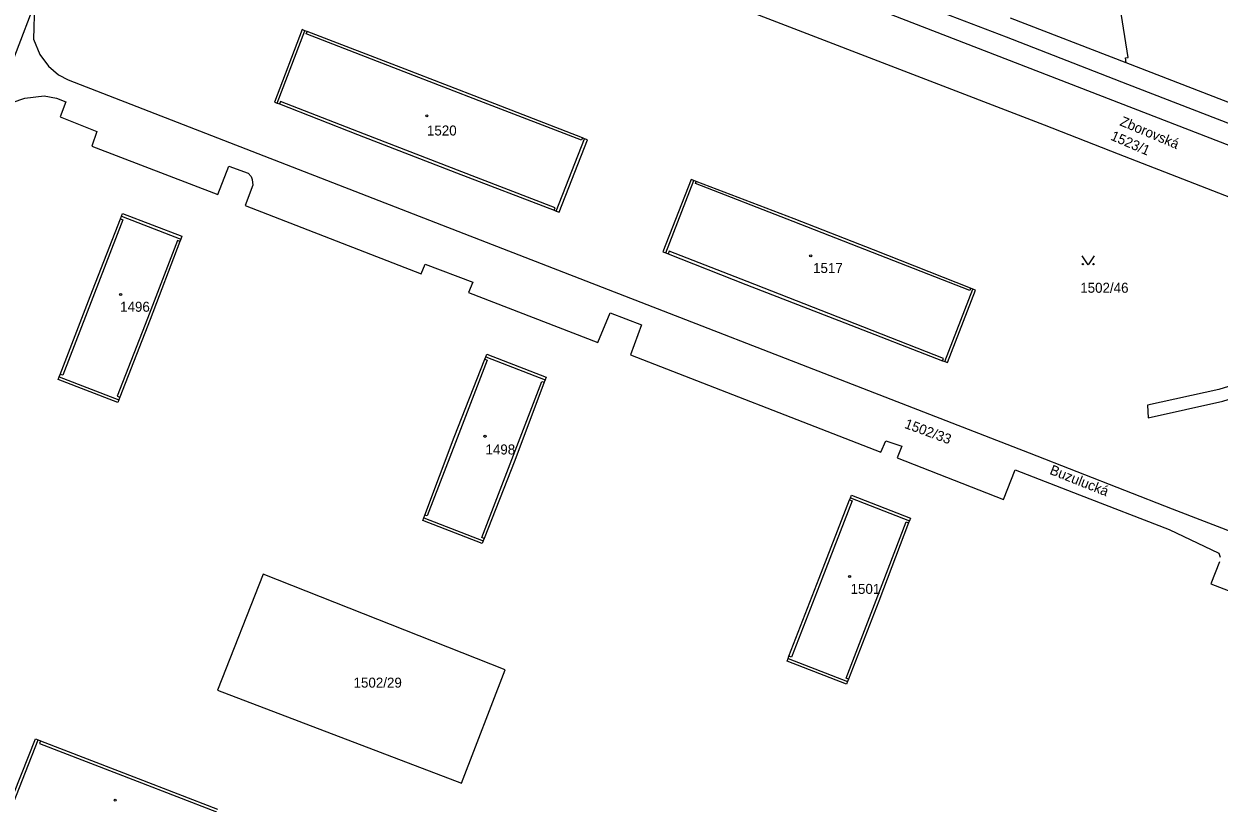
# Model space of a CAD drawing. Extents: x -737240 to -735272, y -1119606 to -1117878.
# Drawn here: x -736749.6 to -736546.3, y -1118575.4 to -1118442.9 of the extents above; entities that cross this region are included whole.
import ezdxf

# ---------------------------------------------------------------- set-up
doc = ezdxf.new("R2010")
doc.units = 0
for name, color, linetype in [('Level 1', 7, 'Continuous'), ('Level 15', 7, 'Continuous'), ('Level 18', 7, 'Continuous'), ('Level 19', 7, 'Continuous'), ('Level 25', 7, 'Continuous'), ('Level 4', 7, 'Continuous')]:
    doc.layers.add(name, color=color, linetype=linetype)

msp = doc.modelspace()

# ---------------------------------------------------------------- linework, layer by layer
at = {"layer": 'Level 1'}
for p, q in [((-736747.83, -1118439.49), (-736756.5, -1118461.9)), ((-736562.09, -1118449.5), (-736581.74, -1118441.93)), ((-736701.44, -1118444.19), (-736701.8, -1118444.05)), ((-736706.51, -1118456.37), (-736706.14, -1118456.51)), ((-736654.21, -1118462.42), (-736654.56, -1118462.28)), ((-736635.22, -1118469.69), (-736635.62, -1118469.53)), ((-736733.2, -1118476.05), (-736733.03, -1118475.61)), ((-736659.38, -1118474.6), (-736659.03, -1118474.74)), ((-736722.91, -1118479.5), (-736723.07, -1118479.91)), ((-736640.41, -1118481.84), (-736640.01, -1118482)), ((-736588.16, -1118487.99), (-736588.54, -1118487.84)), ((-736671.21, -1118499.94), (-736671.05, -1118499.54)), ((-736593.33, -1118500.18), (-736592.94, -1118500.33)), ((-736743.6, -1118502.94), (-736743.44, -1118502.51)), ((-736660.94, -1118503.44), (-736661.1, -1118503.86)), ((-736733.3, -1118506.4), (-736733.46, -1118506.82)), ((-736609.12, -1118523.87), (-736608.98, -1118523.5)), ((-736681.57, -1118526.89), (-736681.4, -1118526.44)), ((-736598.94, -1118527.4), (-736599.09, -1118527.78)), ((-736671.31, -1118530.41), (-736671.47, -1118530.81)), ((-736619.59, -1118550.84), (-736619.45, -1118550.46)), ((-736609.31, -1118554.34), (-736609.46, -1118554.73)), ((-736747.19, -1118564.68), (-736746.78, -1118564.84))]:
    msp.add_line(p, q, dxfattribs=at)
for points in [[(-736738.29, -1118405.68), (-736735.87, -1118406.26), (-736735.1, -1118404.8), (-736733.22, -1118403), (-736731.82, -1118402.29), (-736730.44, -1118401.87), (-736728.42, -1118401.73), (-736726.37, -1118402.09), (-736697.48, -1118413.17), (-736643.97, -1118433.86), (-736576.05, -1118460.06), (-736563.41, -1118465.01), (-736498.48, -1118490.24)], [(-736562.09, -1118449.5), (-736562.21, -1118448.68), (-736561.72, -1118448.62), (-736566.43, -1118418.97), (-736566.87, -1118418.7)], [(-736619.24, -1118430.87), (-736611.06, -1118434.15), (-736582.47, -1118445.12), (-736561.82, -1118453.17), (-736494.82, -1118479.04), (-736481.98, -1118484.08), (-736468.17, -1118487.49), (-736434.16, -1118500.61), (-736418.43, -1118506.54), (-736407.15, -1118511.19), (-736401.23, -1118513.16)], [(-736616.1, -1118435.8), (-736505.66, -1118478.59), (-736444.34, -1118502.39), (-736415.66, -1118513.25), (-736415.08, -1118513.68), (-736401.23, -1118513.16)], [(-736747.83, -1118439.49), (-736747.99, -1118445.49), (-736746.92, -1118448.11), (-736745.44, -1118450.08), (-736743.76, -1118451.55), (-736742.12, -1118452.41), (-736678.57, -1118477.06), (-736578.59, -1118515.84), (-736554.26, -1118525.39), (-736488.43, -1118550.73), (-736484.08, -1118552.14), (-736481.69, -1118552.63), (-736475.63, -1118553.52), (-736465.69, -1118553.51), (-736391.5, -1118550.3)], [(-736701.8, -1118444.05), (-736702.27, -1118443.87), (-736706.98, -1118456.19), (-736706.51, -1118456.37)], [(-736654.56, -1118462.28), (-736671.24, -1118455.79), (-736684.74, -1118450.58), (-736701.44, -1118444.19)], [(-736495.95, -1118474.25), (-736496.27, -1118474.97), (-736562.09, -1118449.5)], [(-736751.62, -1118456.28), (-736749.44, -1118455.55), (-736746.2, -1118455.15), (-736744.09, -1118455.52), (-736742.49, -1118456.15), (-736743.44, -1118458.72), (-736737.19, -1118461.22), (-736738.05, -1118463.72), (-736716.65, -1118471.92), (-736714.75, -1118467.09), (-736711.49, -1118468.31), (-736710.98, -1118468.84), (-736710.76, -1118469.35), (-736710.69, -1118470.31), (-736711.99, -1118473.79), (-736682.01, -1118485.41), (-736681.35, -1118483.79), (-736673.25, -1118486.85), (-736673.95, -1118488.56), (-736651.99, -1118497.11), (-736649.89, -1118492.05), (-736644.54, -1118494.11), (-736646.4, -1118499.19), (-736603.81, -1118515.73), (-736602.95, -1118513.8), (-736600.26, -1118514.73), (-736601.05, -1118516.73), (-736582.96, -1118523.78), (-736580.97, -1118518.77), (-736569.99, -1118522.98), (-736554.74, -1118528.92), (-736546.32, -1118532.9), (-736546.06, -1118533.59)], [(-736706.14, -1118456.51), (-736692.85, -1118461.7), (-736676.01, -1118468.22), (-736659.38, -1118474.6)], [(-736659.03, -1118474.74), (-736658.56, -1118474.92), (-736653.74, -1118462.6), (-736654.21, -1118462.42)], [(-736635.62, -1118469.53), (-736636.09, -1118469.35), (-736640.88, -1118481.66), (-736640.41, -1118481.84)], [(-736588.54, -1118487.84), (-736605.07, -1118481.31), (-736618.54, -1118476.07), (-736635.22, -1118469.69)], [(-736733.03, -1118475.61), (-736732.85, -1118475.14), (-736722.73, -1118479.03), (-736722.91, -1118479.5)], [(-736743.44, -1118502.51), (-736738.36, -1118489.26), (-736733.2, -1118476.05)], [(-736723.07, -1118479.91), (-736728.15, -1118493.18), (-736733.3, -1118506.4)], [(-736640.01, -1118482), (-736626.76, -1118487.2), (-736609.93, -1118493.77), (-736593.33, -1118500.18)], [(-736592.94, -1118500.33), (-736592.47, -1118500.51), (-736587.69, -1118488.17), (-736588.16, -1118487.99)], [(-736498.48, -1118490.24), (-736546.31, -1118505.08), (-736558.45, -1118507.73), (-736558.34, -1118509.9), (-736545.64, -1118507.07), (-736498.8, -1118492.55), (-736496.69, -1118490.89)], [(-736681.4, -1118526.44), (-736676.39, -1118513.18), (-736671.21, -1118499.94)], [(-736671.05, -1118499.54), (-736670.87, -1118499.07), (-736660.76, -1118502.97), (-736660.94, -1118503.44)], [(-736733.46, -1118506.82), (-736733.64, -1118507.29), (-736743.78, -1118503.41), (-736743.6, -1118502.94)], [(-736661.1, -1118503.86), (-736666.11, -1118517.16), (-736671.31, -1118530.41)], [(-736619.45, -1118550.46), (-736614.33, -1118537.15), (-736609.12, -1118523.87)], [(-736608.98, -1118523.5), (-736608.8, -1118523.04), (-736598.76, -1118526.94), (-736598.94, -1118527.4)], [(-736671.47, -1118530.81), (-736671.65, -1118531.28), (-736681.75, -1118527.36), (-736681.57, -1118526.89)], [(-736599.09, -1118527.78), (-736604.15, -1118541.08), (-736609.31, -1118554.34)], [(-736546.2, -1118534.42), (-736547.68, -1118538.14), (-736522.12, -1118547.96)], [(-736708.92, -1118536.49), (-736716.71, -1118556.23), (-736675.16, -1118572.05), (-736667.71, -1118552.74), (-736708.92, -1118536.49)], [(-736609.46, -1118554.73), (-736609.64, -1118555.2), (-736619.77, -1118551.31), (-736619.59, -1118550.84)], [(-736752.03, -1118577), (-736752.5, -1118576.82), (-736747.66, -1118564.5), (-736747.19, -1118564.68)], [(-736746.78, -1118564.84), (-736730.16, -1118571.23), (-736716.68, -1118576.44)]]:
    msp.add_lwpolyline(points, dxfattribs=at)
at = {"layer": 'Level 25'}
msp.add_lwpolyline([(-736567.54, -1118482.35), (-736568.54, -1118483.85), (-736569.54, -1118482.35)], dxfattribs=at)
for centre in [(-736569.44, -1118483.75), (-736567.64, -1118483.75)]:
    msp.add_circle(centre, 0.1, dxfattribs=at)
for centre in [(-736681.06, -1118458.52), (-736615.75, -1118482.34), (-736733.16, -1118488.91), (-736671.16, -1118513.04), (-736609.13, -1118536.9), (-736734.09, -1118574.94)]:
    msp.add_ellipse(centre, major_axis=(0.18, 0), ratio=0.9848078, dxfattribs=at)
at = {"layer": 'Level 4'}
for p, q in [((-736706.51, -1118456.37), (-736701.8, -1118444.05)), ((-736659.03, -1118474.74), (-736654.21, -1118462.42)), ((-736640.41, -1118481.84), (-736635.62, -1118469.53)), ((-736733.03, -1118475.61), (-736722.91, -1118479.5)), ((-736592.94, -1118500.33), (-736588.16, -1118487.99)), ((-736671.05, -1118499.54), (-736660.94, -1118503.44)), ((-736743.6, -1118502.94), (-736733.46, -1118506.82)), ((-736608.98, -1118523.5), (-736598.94, -1118527.4)), ((-736681.57, -1118526.89), (-736671.47, -1118530.81)), ((-736619.59, -1118550.84), (-736609.46, -1118554.73)), ((-736752.03, -1118577), (-736747.19, -1118564.68))]:
    msp.add_line(p, q, dxfattribs=at)
for points in [[(-736654.56, -1118462.28), (-736654.73, -1118462.69), (-736671.42, -1118456.25), (-736684.92, -1118451.04), (-736701.6, -1118444.61), (-736701.44, -1118444.19)], [(-736659.38, -1118474.6), (-736659.22, -1118474.18), (-736675.83, -1118467.76), (-736692.67, -1118461.24), (-736705.98, -1118456.09), (-736706.14, -1118456.51)], [(-736588.54, -1118487.84), (-736588.68, -1118488.22), (-736605.25, -1118481.77), (-736618.72, -1118476.53), (-736635.36, -1118470.06), (-736635.22, -1118469.69)], [(-736733.2, -1118476.05), (-736732.78, -1118476.21), (-736737.89, -1118489.44), (-736743.01, -1118502.67), (-736743.44, -1118502.51)], [(-736723.07, -1118479.91), (-736723.49, -1118479.75), (-736728.62, -1118493), (-736733.73, -1118506.23), (-736733.3, -1118506.4)], [(-736593.33, -1118500.18), (-736593.17, -1118499.79), (-736609.75, -1118493.31), (-736626.57, -1118486.73), (-736639.83, -1118481.55), (-736640.01, -1118482)], [(-736671.21, -1118499.94), (-736670.81, -1118500.09), (-736675.92, -1118513.36), (-736681.02, -1118526.59), (-736681.4, -1118526.44)], [(-736671.31, -1118530.41), (-736671.69, -1118530.26), (-736666.58, -1118516.98), (-736661.47, -1118503.72), (-736661.1, -1118503.86)], [(-736609.12, -1118523.87), (-736608.71, -1118524.03), (-736613.87, -1118537.33), (-736619.02, -1118550.63), (-736619.45, -1118550.46)], [(-736609.31, -1118554.34), (-736609.71, -1118554.18), (-736604.62, -1118540.9), (-736599.52, -1118527.61), (-736599.09, -1118527.78)], [(-736746.78, -1118564.84), (-736746.95, -1118565.27), (-736730.34, -1118571.69), (-736716.86, -1118576.91)]]:
    msp.add_lwpolyline(points, dxfattribs=at)

# ---------------------------------------------------------------- texts
at = {"layer": 'Level 15'}
for s, rotation, p in [('Zborovská', 337.25331, (-736563.292, -1118460.109)), ('Buzulucká', 338.33403, (-736575.215, -1118519.412))]:
    msp.add_text(s, height=1.7, rotation=rotation, dxfattribs=at).set_placement(p)
at = {"layer": 'Level 18'}
for s, rotation, p in [('1523/1', 336.57129, (-736564.85, -1118462.564)), ('1502/33', 339.7914, (-736599.918, -1118511.588))]:
    msp.add_text(s, height=1.7, rotation=rotation, dxfattribs=at).set_placement(p)
for s, p in [('1502/46', (-736569.885, -1118488.63)), ('1502/29', (-736693.535, -1118555.79))]:
    msp.add_text(s, height=1.7, dxfattribs=at).set_placement(p)
at = {"layer": 'Level 19'}
for s, p in [('1520', (-736681.045, -1118461.88)), ('1517', (-736615.345, -1118485.27)), ('1496', (-736733.255, -1118491.86)), ('1498', (-736671.085, -1118516.13)), ('1501', (-736608.965, -1118539.85))]:
    msp.add_text(s, height=1.7, dxfattribs=at).set_placement(p)

doc.saveas('drawing.dxf')
